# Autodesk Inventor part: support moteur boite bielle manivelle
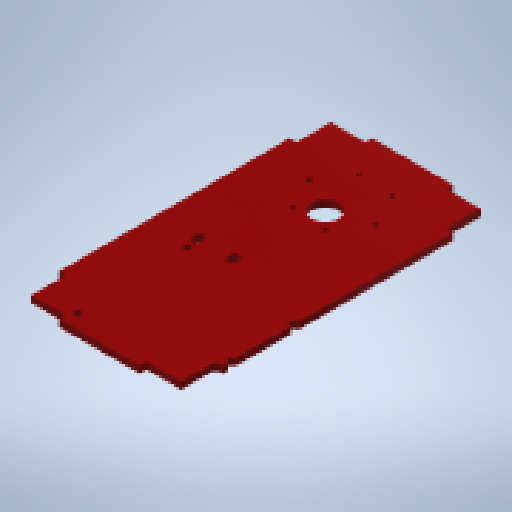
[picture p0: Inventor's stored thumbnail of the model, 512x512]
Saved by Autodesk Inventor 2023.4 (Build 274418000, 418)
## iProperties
Part Number: support moteur boite bielle manivelle
Material: Générique
Document SubType Name: Modeling
Designer: ficho
Density: 1 g/cm^3
Appearance: Rouge
Author: ficho
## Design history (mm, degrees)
sketch "Esquisse1"
  geometry: L1 (0, 0)-(65, 0); L2 (65, 0)-(65, 130); L3 (65, 130)-(0, 130); L4 (0, 130)-(0, 0); L5 (15, 130)-(50, 130); L6 (50, 130)-(50, 133); L7 (50, 133)-(15, 133); L8 (15, 133)-(15, 130); L9 (0, 115)-(-3, 115); L10 (-3, 115)-(-3, 15); L11 (-3, 15)-(0, 15); L12 (0, 15)-(0, 115); L13 (65, 115)-(68, 115); L14 (68, 115)-(68, 15); L15 (68, 15)-(65, 15); L16 (65, 15)-(65, 115); L17 (15, 0)-(50, 0); L18 (50, 0)-(50, -3); L19 (50, -3)-(15, -3); L20 (15, -3)-(15, 0)
  constraints: 40 end point, 10 parallel, 5 horizontal, 5 perpendicular, 4 point on line
  dimensions: "d0" = 65 distance of L3.end L2.end (= 0.5 x d1); "d1" = 130 distance of L2.end L1.end; "d2" = 35 distance of L7.end L6.end (computed from d0); "d3" = 3 distance of L6.end L5.end; "d4" = 15 distance between parallel lines of L4 L8 (= -0.5 x d2 + 0.5 x d0); "d5" = 3 distance between parallel lines of L4 L10 (= d3); "d6" = 15 distance between parallel lines of L3 L9 (= -0.5 x d7 + 0.5 x d1); "d7" = 100 distance between parallel lines of L11 L9 (computed from d1); "d8" = 3 distance between parallel lines of L14 L2 (= d5); "d9" = 100 distance between parallel lines of L15 L13 (= d7); "d10" = 15 distance between parallel lines of L13 L3 (= d6); "d11" = 15 distance between parallel lines of L20 L4 (= d6); "d12" = 35 distance between parallel lines of L18 L20 (= d2); "d13" = 3 distance between parallel lines of L19 L17 (= d5)
extrude "Extrusion1" new body sketch "Esquisse1" distance "d14" = 3 (= d3); taper "d15" = 0 deg
sketch "Esquisse2"
  geometry: L1 (0, 130)-(0, 115) reference; L2 (65, 0)-(65, 15) reference; L3 (50, 133)-(15, 133) reference; C1 r 6 at (32.052, 95.543); C2 r 1.23 at (39.257, 88.579); C3 r 1.23 at (41.202, 115.355); C4 r 1.23 at (17.041, 103.651); C5 r 1.23 at (25.743, 116.478); C6 r 1.23 at (47.959, 101.405); C7 r 1.23 at (23.798, 89.702); C8 r 18.25 at (32.5, 102.528); 3 further points
  constraints: 8 centre point
  dimensions: "d18" = 30.472 distance from line of point (32.5, 102.528) L3
extrude "Extrusion2" cut sketch "Esquisse2" extent not by distance; stored distance "d16" = 3 (= d3); taper "d17" = 0 deg
sketch "Esquisse4"
  geometry: L1 (122.728, 47.735)-(124.478, 47.735); L2 (122.728, 44.235)-(124.478, 44.235); L3 (122.728, 32.54)-(124.478, 32.54); L4 (122.728, 29.04)-(124.478, 29.04); A1 r 1.75 centre (122.728, 45.985) between (122.728, 47.735) and (122.728, 44.235); A2 r 1.75 centre (122.728, 30.79) between (122.728, 32.54) and (122.728, 29.04); A3 r 1.75 centre (124.478, 45.985) between (124.478, 44.235) and (124.478, 47.735); A4 r 1.75 centre (124.478, 30.79) between (124.478, 29.04) and (124.478, 32.54); 1 further point
  constraints: 10 point on circle, 8 end point, 4 centre point
  dimensions: "d22" = 3.5 diameter of A3; "d23" = 3.5 diameter of A4
extrude "Extrusion4" cut sketch "Esquisse4" extent not by distance; stored distance "d24" = 3; taper "d25" = 0 deg
sketch "Esquisse5"
  geometry: L1 (13.06, 58.422)-(13.06, 56.672); L2 (16.56, 58.422)-(16.56, 56.672); L3 (28.256, 58.422)-(28.256, 56.672); L4 (31.756, 58.422)-(31.756, 56.672); A1 r 1.75 centre (14.81, 56.672) between (13.06, 56.672) and (16.56, 56.672); A2 r 1.75 centre (30.006, 56.672) between (28.256, 56.672) and (31.756, 56.672); A3 r 1.75 centre (14.81, 58.422) between (16.56, 58.422) and (13.06, 58.422); A4 r 1.75 centre (30.006, 58.422) between (31.756, 58.422) and (28.256, 58.422); 1 further point
  constraints: 12 point on circle, 8 end point, 4 centre point
extrude "Extrusion5" cut sketch "Esquisse5" extent not by distance; stored distance "d26" = 3; taper "d27" = 0 deg
sketch "Esquisse6"
  geometry: C1 r 1.588 at (-15.875, 51.8) reference; C2 r 1.587 at (-16.945, 3.291) reference; C3 r 1.587 at (-67.745, 46.471) reference; C4 r 1.588 at (-67.945, 18.78) reference; 1 further point
extrude "Extrusion6" cut sketch "Esquisse6" extent not by distance; stored distance "d28" = 3; taper "d29" = 0 deg
fillet "Congé1" dims "d30" = 2
node "Solide1"
node "Référence6"
node "Référence7"
node "Référence8"
node "Référence9"
